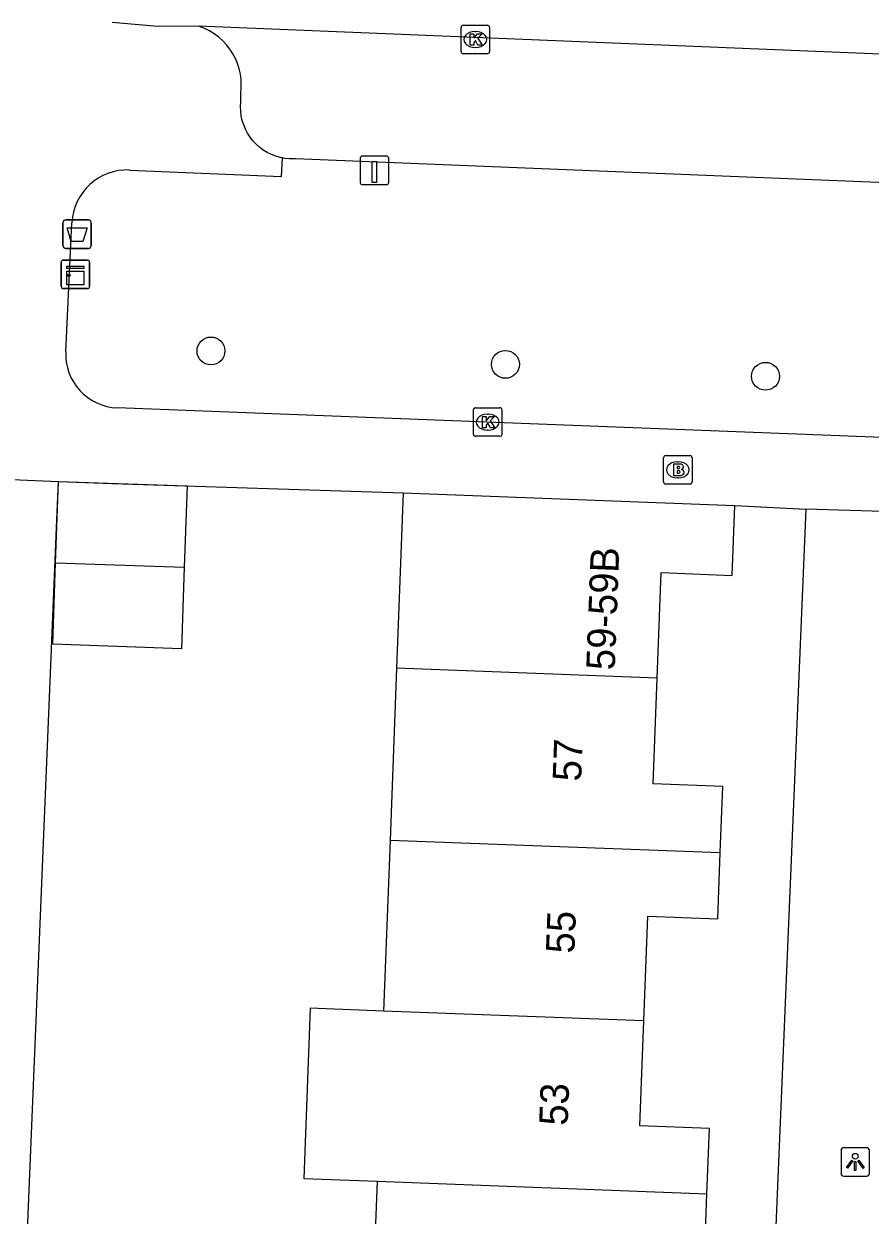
# Model space of a CAD drawing. Extents: x 160787 to 161428, y 386828 to 387483.
# Drawn here: x 161141.08 to 161170.76, y 387352.18 to 387393.95 of the extents above; entities that cross this region are included whole.
import ezdxf

# ---------------------------------------------------------------- set-up
doc = ezdxf.new("R2010")
doc.units = 0
for name, color, linetype in [('IMGEO_Afvalbak', 7, 'Continuous'), ('IMGEO_Boom', 7, 'Continuous'), ('IMGEO_Brandkraan', 7, 'Continuous'), ('IMGEO_Kast', 7, 'Continuous'), ('IMGEO_Kolk', 7, 'Continuous'), ('IMGEO_Laadpaal', 7, 'Continuous'), ('IMGEO_Lichtpunt', 7, 'Continuous'), ('IMGEO_Pand', 7, 'Continuous'), ('IMGEO_Pand_nummerreeks', 7, 'Continuous'), ('IMGEO_Pand_vergunning_verleend', 7, 'Continuous'), ('IMGEO_Parkeervlak_open', 7, 'Continuous'), ('IMGEO_Rijbaan_lokaal_gesloten', 7, 'Continuous'), ('IMGEO_Voetpad_open', 7, 'Continuous')]:
    doc.layers.add(name, color=color, linetype=linetype)

msp = doc.modelspace()

# ---------------------------------------------------------------- linework, layer by layer
at = {"layer": 'IMGEO_Afvalbak'}
for p, q in [((161142.451, 387386.179), (161142.451, 387386.979)), ((161142.451, 387386.979), (161142.451, 387386.179)), ((161142.551, 387387.079), (161143.341, 387387.079)), ((161143.341, 387387.079), (161142.551, 387387.079)), ((161143.441, 387386.979), (161143.441, 387386.179)), ((161143.441, 387386.179), (161143.441, 387386.979)), ((161143.341, 387386.079), (161142.551, 387386.079)), ((161142.551, 387386.079), (161143.341, 387386.079))]:
    msp.add_line(p, q, dxfattribs=at)
msp.add_lwpolyline([(161142.594, 387386.793), (161143.298, 387386.793), (161143.149, 387386.323), (161142.743, 387386.323), (161142.594, 387386.793)], dxfattribs=at)
for centre, start, end in [((161142.551, 387386.979), 90, 180), ((161142.551, 387386.979), 90, 180), ((161143.341, 387386.979), 0, 90), ((161143.341, 387386.979), 360, 90), ((161142.551, 387386.179), 180, 270), ((161142.551, 387386.179), 180, 270), ((161143.341, 387386.179), 270, 0), ((161143.341, 387386.179), 270, 0)]:
    msp.add_arc(centre, 0.1, start, end, dxfattribs=at)
at = {"layer": 'IMGEO_Boom'}
for centre in [(161147.64, 387382.481), (161157.966, 387382.012), (161167.085, 387381.593)]:
    msp.add_circle(centre, 0.489, dxfattribs=at)
at = {"layer": 'IMGEO_Brandkraan'}
for p, q in [((161163.511, 387377.887), (161163.511, 387378.739)), ((161163.586, 387378.813), (161164.438, 387378.813)), ((161163.999, 387378.593), (161164.024, 387378.593)), ((161164.512, 387378.739), (161164.512, 387377.887)), ((161164.438, 387377.813), (161163.586, 387377.813)), ((161164.022, 387378.033), (161163.997, 387378.033))]:
    msp.add_line(p, q, dxfattribs=at)
for points in [[(161163.511, 387377.887), (161163.511, 387378.739)], [(161163.586, 387378.813), (161164.438, 387378.813)], [(161164.512, 387378.739), (161164.512, 387377.887)], [(161163.859, 387378.513), (161163.859, 387378.113), (161164.072, 387378.113)], [(161164.09, 387378.513), (161163.859, 387378.513)], [(161164.038, 387378.432), (161163.984, 387378.432), (161163.984, 387378.356)], [(161163.984, 387378.356), (161164.037, 387378.356)], [(161164.046, 387378.28), (161163.984, 387378.28), (161163.984, 387378.199)], [(161163.984, 387378.199), (161164.046, 387378.199)], [(161164.438, 387377.813), (161163.586, 387377.813)]]:
    msp.add_lwpolyline(points, dxfattribs=at)
for centre, radius, start, end in [((161163.588, 387378.737), 0.0765, 91.552, 178.448), ((161163.588, 387378.737), 0.0765, 91.552, 178.448), ((161164.436, 387378.737), 0.0765, 1.552, 88.448), ((161164.436, 387378.737), 0.0765, 1.552, 88.448), ((161164.039, 387378.394), 0.0379, 267.8285, 90.9355), ((161164.047, 387378.239), 0.0404, 269.8759, 90.5077), ((161164.094, 387378.368), 0.145, 59.4692, 91.5367), ((161164.119, 387378.415), 0.0922, 285.5137, 58.1501), ((161164.124, 387378.223), 0.105, 301.3115, 78.989), ((161163.588, 387377.889), 0.0765, 181.552, 268.448), ((161163.588, 387377.889), 0.0765, 181.552, 268.448), ((161164.078, 387378.364), 0.251, 268.6676, 293.5347), ((161164.436, 387377.889), 0.0765, 271.552, 358.448), ((161164.436, 387377.889), 0.0765, 271.552, 358.448)]:
    msp.add_arc(centre, radius, start, end, dxfattribs=at)
for centre, major_axis, ratio, start_param, end_param in [((161163.998, 387378.313), (-0.387, 0.002), 0.722429, 4.712389, 7.853982), ((161164.023, 387378.313), (-0.39, 0.002), 0.717154, 1.570796, 4.712389)]:
    msp.add_ellipse(centre, major_axis=major_axis, ratio=ratio, start_param=start_param, end_param=end_param, dxfattribs=at)
at = {"layer": 'IMGEO_Kast'}
for p, q in [((161142.386, 387384.744), (161142.386, 387385.585)), ((161142.386, 387385.585), (161142.386, 387384.744)), ((161142.461, 387385.669), (161143.302, 387385.669)), ((161143.302, 387385.669), (161142.461, 387385.669)), ((161143.386, 387385.594), (161143.386, 387384.753)), ((161143.386, 387384.753), (161143.386, 387385.594)), ((161143.311, 387384.669), (161142.47, 387384.669)), ((161142.47, 387384.669), (161143.311, 387384.669))]:
    msp.add_line(p, q, dxfattribs=at)
for points in [[(161142.581, 387385.459), (161143.181, 387385.459), (161143.181, 387385.374), (161142.581, 387385.374), (161142.581, 387385.459)], [(161142.581, 387385.284), (161143.181, 387385.284), (161143.181, 387384.795), (161142.581, 387384.795), (161142.581, 387385.284)]]:
    msp.add_lwpolyline(points, dxfattribs=at)
msp.add_circle((161142.665, 387385.133), 0.0377, dxfattribs=at)
for centre, start, end in [((161142.464, 387385.591), 92.4484, 184.2845), ((161142.464, 387385.591), 92.4484, 184.2845), ((161143.308, 387385.591), 2.4484, 94.2845), ((161143.308, 387385.591), 2.4484, 94.2845), ((161142.464, 387384.747), 182.4484, 274.2845), ((161142.464, 387384.747), 182.4484, 274.2845), ((161143.308, 387384.747), 272.4484, 4.2845), ((161143.308, 387384.747), 272.4484, 4.2845)]:
    msp.add_arc(centre, 0.0779, start, end, dxfattribs=at)
at = {"layer": 'IMGEO_Kolk'}
for p, q in [((161156.409, 387392.976), (161156.409, 387393.828)), ((161156.484, 387393.902), (161157.336, 387393.902)), ((161156.897, 387393.682), (161156.922, 387393.682)), ((161157.41, 387393.828), (161157.41, 387392.976)), ((161157.336, 387392.902), (161156.484, 387392.902)), ((161156.92, 387393.122), (161156.895, 387393.122)), ((161156.844, 387379.562), (161156.844, 387380.414)), ((161156.919, 387380.488), (161157.771, 387380.488)), ((161157.332, 387380.268), (161157.357, 387380.268)), ((161157.845, 387380.414), (161157.845, 387379.562)), ((161157.771, 387379.488), (161156.919, 387379.488)), ((161157.355, 387379.708), (161157.33, 387379.708))]:
    msp.add_line(p, q, dxfattribs=at)
for points in [[(161156.409, 387392.976), (161156.409, 387393.828)], [(161156.484, 387393.902), (161157.336, 387393.902)], [(161157.41, 387393.828), (161157.41, 387392.976)], [(161156.73, 387393.602), (161156.853, 387393.602), (161156.853, 387393.451), (161156.983, 387393.602), (161157.147, 387393.602), (161157.001, 387393.451), (161157.154, 387393.202), (161157.002, 387393.202), (161156.917, 387393.366), (161156.853, 387393.299), (161156.853, 387393.202), (161156.73, 387393.202), (161156.73, 387393.602)], [(161157.336, 387392.902), (161156.484, 387392.902)], [(161156.844, 387379.562), (161156.844, 387380.414)], [(161156.919, 387380.488), (161157.771, 387380.488)], [(161157.845, 387380.414), (161157.845, 387379.562)], [(161157.165, 387380.188), (161157.288, 387380.188), (161157.288, 387380.037), (161157.418, 387380.188), (161157.582, 387380.188), (161157.436, 387380.037), (161157.589, 387379.788), (161157.437, 387379.788), (161157.352, 387379.952), (161157.288, 387379.885), (161157.288, 387379.788), (161157.165, 387379.788), (161157.165, 387380.188)], [(161157.771, 387379.488), (161156.919, 387379.488)]]:
    msp.add_lwpolyline(points, dxfattribs=at)
for centre, start, end in [((161156.486, 387393.826), 91.552, 178.448), ((161156.486, 387393.826), 91.552, 178.448), ((161157.334, 387393.826), 1.552, 88.448), ((161157.334, 387393.826), 1.552, 88.448), ((161156.486, 387392.978), 181.552, 268.448), ((161156.486, 387392.978), 181.552, 268.448), ((161157.334, 387392.978), 271.552, 358.448), ((161157.334, 387392.978), 271.552, 358.448), ((161156.921, 387380.412), 91.552, 178.448), ((161156.921, 387380.412), 91.552, 178.448), ((161157.769, 387380.412), 1.552, 88.448), ((161157.769, 387380.412), 1.552, 88.448), ((161156.921, 387379.564), 181.552, 268.448), ((161156.921, 387379.564), 181.552, 268.448), ((161157.769, 387379.564), 271.552, 358.448), ((161157.769, 387379.564), 271.552, 358.448)]:
    msp.add_arc(centre, 0.0765, start, end, dxfattribs=at)
for centre, major_axis, ratio, start_param, end_param in [((161156.896, 387393.402), (-0.387, 0.002), 0.722429, 4.712389, 7.853982), ((161156.921, 387393.402), (-0.39, 0.002), 0.717154, 1.570796, 4.712389), ((161157.331, 387379.988), (-0.387, 0.002), 0.722429, 4.712389, 7.853982), ((161157.356, 387379.988), (-0.39, 0.002), 0.717154, 1.570796, 4.712389)]:
    msp.add_ellipse(centre, major_axis=major_axis, ratio=ratio, start_param=start_param, end_param=end_param, dxfattribs=at)
at = {"layer": 'IMGEO_Laadpaal'}
for p, q in [((161152.872, 387389.229), (161152.872, 387388.388)), ((161152.872, 387389.229), (161152.872, 387388.388)), ((161153.788, 387389.313), (161152.947, 387389.313)), ((161153.788, 387389.313), (161152.947, 387389.313)), ((161153.872, 387388.397), (161153.872, 387389.238)), ((161153.872, 387388.397), (161153.872, 387389.238)), ((161152.956, 387388.313), (161153.797, 387388.313)), ((161152.956, 387388.313), (161153.797, 387388.313))]:
    msp.add_line(p, q, dxfattribs=at)
msp.add_lwpolyline([(161153.287, 387389.126), (161153.447, 387389.126), (161153.447, 387388.393), (161153.287, 387388.393), (161153.287, 387389.126)], dxfattribs=at)
for centre, start, end in [((161152.95, 387389.235), 92.4484, 184.2845), ((161152.95, 387389.235), 92.4484, 184.2845), ((161153.794, 387389.235), 2.4484, 94.2845), ((161153.794, 387389.235), 2.4484, 94.2845), ((161152.95, 387388.391), 182.4484, 274.2845), ((161152.95, 387388.391), 182.4484, 274.2845), ((161153.794, 387388.391), 272.4484, 4.2845), ((161153.794, 387388.391), 272.4484, 4.2845)]:
    msp.add_arc(centre, 0.0779, start, end, dxfattribs=at)
at = {"layer": 'IMGEO_Lichtpunt'}
for p, q in [((161169.733, 387354.449), (161169.733, 387353.642)), ((161169.733, 387354.449), (161169.733, 387353.642)), ((161170.635, 387354.544), (161169.827, 387354.544)), ((161170.635, 387354.544), (161169.827, 387354.544)), ((161170.729, 387353.642), (161170.729, 387354.449)), ((161170.729, 387353.642), (161170.729, 387354.449)), ((161169.827, 387353.548), (161170.635, 387353.548)), ((161169.827, 387353.548), (161170.635, 387353.548))]:
    msp.add_line(p, q, dxfattribs=at)
for points in [[(161170.107, 387354.113), (161170.146, 387354.085), (161169.958, 387353.823), (161169.92, 387353.85), (161170.107, 387354.113)], [(161170.209, 387354.065), (161170.256, 387354.065), (161170.256, 387353.743), (161170.209, 387353.743), (161170.209, 387354.065)], [(161170.319, 387354.085), (161170.357, 387354.112), (161170.544, 387353.85), (161170.505, 387353.822), (161170.319, 387354.085)]]:
    msp.add_lwpolyline(points, dxfattribs=at)
msp.add_circle((161170.232, 387354.247), 0.0994, dxfattribs=at)
for centre, start, end in [((161169.827, 387354.449), 90, 180), ((161169.827, 387354.449), 90, 180), ((161170.635, 387354.449), 0, 90), ((161170.635, 387354.449), 0, 90), ((161169.827, 387353.642), 180, 270), ((161169.827, 387353.642), 180, 270), ((161170.635, 387353.642), 270, 0), ((161170.635, 387353.642), 270, 360)]:
    msp.add_arc(centre, 0.0946, start, end, dxfattribs=at)
at = {"layer": 'IMGEO_Pand'}
for points in [[(161154.385, 387377.506), (161154.15, 387371.357)], [(161154.385, 387377.506), (161166.008, 387377.063)], [(161163.288, 387371.008), (161163.429, 387374.709), (161165.915, 387374.614), (161166.008, 387377.063)], [(161154.15, 387371.357), (161153.921, 387365.334)], [(161163.288, 387371.008), (161154.15, 387371.357)], [(161165.498, 387364.892), (161165.587, 387367.21), (161163.146, 387367.303), (161163.288, 387371.008)], [(161153.921, 387365.334), (161153.692, 387359.338)], [(161153.921, 387365.334), (161165.498, 387364.892)], [(161162.815, 387358.99), (161162.955, 387362.668), (161165.41, 387362.575), (161165.498, 387364.892)], [(161153.692, 387359.338), (161151.121, 387359.436), (161150.893, 387353.468), (161153.464, 387353.37)], [(161162.815, 387358.99), (161153.692, 387359.338)], [(161165.031, 387352.928), (161165.118, 387355.215), (161162.674, 387355.309), (161162.815, 387358.99)], [(161153.464, 387353.37), (161153.237, 387347.412)], [(161153.464, 387353.37), (161165.031, 387352.928)], [(161162.336, 387347.065), (161162.476, 387350.733), (161164.943, 387350.639), (161165.031, 387352.928)]]:
    msp.add_lwpolyline(points, dxfattribs=at)
at = {"layer": 'IMGEO_Pand_vergunning_verleend'}
for points in [[(161142.192, 387375.056), (161142.294, 387377.909), (161146.808, 387377.748), (161146.706, 387374.895)], [(161146.706, 387374.895), (161146.604, 387372.042), (161142.09, 387372.203), (161142.192, 387375.056)], [(161142.192, 387375.056), (161146.706, 387374.895)]]:
    msp.add_lwpolyline(points, dxfattribs=at)
at = {"layer": 'IMGEO_Parkeervlak_open'}
msp.add_lwpolyline([(161172.764, 387388.317), (161150.608, 387389.217), (161150.549, 387389.214), (161150.386, 387389.217), (161150.225, 387389.234), (161150.146, 387389.249)], dxfattribs=at)
at = {"layer": 'IMGEO_Rijbaan_lokaal_gesloten'}
for points in [[(161147.201, 387393.867), (161145.778, 387393.861), (161144.181, 387394)], [(161201.019, 387391.663), (161147.201, 387393.867)]]:
    msp.add_lwpolyline(points, dxfattribs=at)
at = {"layer": 'IMGEO_Voetpad_open'}
for points in [[(161150.146, 387389.249), (161150.066, 387389.265), (161149.91, 387389.31), (161149.758, 387389.369), (161149.613, 387389.442), (161149.475, 387389.527), (161149.344, 387389.624), (161149.223, 387389.732), (161149.113, 387389.851), (161149.013, 387389.979), (161148.925, 387390.116), (161148.85, 387390.26), (161148.787, 387390.41), (161148.739, 387390.565), (161148.704, 387390.723), (161148.684, 387390.885), (161148.678, 387391.047), (161148.687, 387391.209), (161148.7, 387391.996), (161148.675, 387392.187), (161148.633, 387392.375), (161148.575, 387392.558), (161148.501, 387392.735), (161148.411, 387392.905), (161148.306, 387393.067), (161148.187, 387393.218), (161148.055, 387393.358), (161147.911, 387393.486), (161147.757, 387393.6), (161147.592, 387393.7), (161147.42, 387393.785), (161147.24, 387393.854), (161147.201, 387393.867)], [(161144.785, 387388.826), (161150.119, 387388.603), (161150.146, 387389.249)], [(161172.764, 387388.317), (161172.737, 387387.66), (161172.633, 387385.162), (161172.498, 387381.904), (161172.395, 387379.406), (161144.355, 387380.487)], [(161142.548, 387382.456), (161142.762, 387386.976)], [(161136.309, 387378.159), (161142.294, 387377.909)], [(161139.046, 387299.512), (161142.214, 387375.996), (161142.215, 387376.018), (161142.294, 387377.909)], [(161142.294, 387377.909), (161144.171, 387377.831), (161154.385, 387377.506)], [(161166.008, 387377.063), (161168.496, 387376.93)], [(161168.496, 387376.93), (161166.813, 387336.716)], [(161176.241, 387376.703), (161168.496, 387376.93)]]:
    msp.add_lwpolyline(points, dxfattribs=at)
for centre, radius, start, end in [((161144.704, 387386.883), 1.945, 87.626, 177.2588), ((161144.427, 387382.367), 1.881, 177.2859, 267.8009)]:
    msp.add_arc(centre, radius, start, end, dxfattribs=at)

# ---------------------------------------------------------------- texts
at = {"layer": 'IMGEO_Pand_nummerreeks'}
for s, rotation, p in [('59-59B', 87.8172, (161161.797, 387371.275)), ('57', 87.7523, (161160.617, 387367.378)), ('55', 87.7523, (161160.381, 387361.343)), ('53', 87.7542, (161160.144, 387355.307))]:
    msp.add_text(s, height=1, rotation=rotation, dxfattribs=at).set_placement(p)

doc.saveas('drawing.dxf')
